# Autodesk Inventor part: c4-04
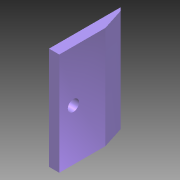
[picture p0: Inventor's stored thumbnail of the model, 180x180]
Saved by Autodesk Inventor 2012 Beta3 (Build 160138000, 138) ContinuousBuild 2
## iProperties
Created: 2010-11
Part Number: c4-04
Material: Default
Document SubType Name: Modeling
Designer: Beta-8540w
Density: 1 g/cm^3
Author: Beta-8540w
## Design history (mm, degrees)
sketch "Sketch1"
  geometry: L1 (0, 0)-(10, 0); L2 (10, 0)-(10, 70); L3 (10, 70)-(0, 70); L4 (0, 70)-(0, 0); L5 (3, 67)-(10, 45); L6 (0, 70)-(3, 67); 1 further point
  constraints: 12 end point, 2 parallel, 2 point on line, 1 horizontal, 1 perpendicular
  dimensions: "d0" = 10 distance of L3.end L2.end; "d1" = 70 distance of L2.end L1.end; "d3" = 25 vertical distance of point (2.045, 70) L5.end; "d6" = 45 deg angle of L4 L6; "d7" = 3 distance from line of L4 L5.start
extrude "Extrusion1" new body sketch "Sketch1" stored distance "d4" = 100; taper "d5" = 0 deg
hole "Hole1" diameter "d10" = 11; stored, may be unused: countersink angle "d14" = 90 deg, drill point angle "d16" = 118 deg; dims "d8" = 50, "d9" = 13.8, "d11" = 6, "d12" = 4, "d13" = 90, "d15" = 8
body "Solid1"
